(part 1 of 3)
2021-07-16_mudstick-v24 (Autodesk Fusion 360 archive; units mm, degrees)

design "Mudstick" references "N17 48mm", "2298K420_METRIC QUICK-GRIP SCREW-CLAMP BUSHING", "Mudstick Plate"
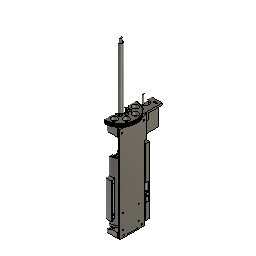
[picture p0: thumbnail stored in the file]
parameter "flexure_w" = 1.5
parameter "gap_w" = 1
parameter "t_sheet_main" = 6.6
parameter "tube_wallthick" = 3.3
parameter "tube_id" = 50.6
parameter "tube_len" = 149.225 (= "( 6 * 25.4 ) * 1 mm - ( 0.125 * 25.4 ) * 1 mm")
parameter "id_bspushbearing" = 40
parameter "od_bspushbearing" = 52
parameter "t_bspushbearing" = 7
parameter "hw_m4insert_d" = 5.8
parameter "hw_m4insert_l" = 4.6
parameter "p_teeth" = 2
parameter "pd_pinion" = 10.1859 (= "p_teeth * nt_pinion / PI")
parameter "pd_driven" = 81.4873 (= "p_teeth * nt_driven / PI")
parameter "belt_length" = 280
parameter "c_dist_manuel" = 56.6
parameter "d101" = 7 (= "t_bspushbearing")
parameter "d118" = 2.15 (= "( 4.3 / 2 ) * 1 mm")
sketch "Sketch1" plane through (0, 0, 0) normal (0, 1, 0) x axis (1, 0, 0)
  line L1 (70, 0) -> (0, 0)
  line L2 (70, -115) -> (70, 0)
  line L3 (0, -115) -> (70, -115)
  line L4 (0, 0) -> (0, -115)
  line L5 (35, 0) -> (35, -115)
  point P1 (0, 0)
  point P2 (0, 0)
  point P6 (35, -115)
  point P7 (35, 0)
  point P4 (70, -115)
  point P5 (0, -115)
  horizontal L1
  vertical L2
  horizontal L3
  coincident P1 P2
  vertical L4
  midpoint L3 P6
  midpoint L1 P7
  dimension "d1" distance P4 P5 = 70
  dimension "d2" distance P2 P5 = 115
extrude "Extrude3" new body sketch "Sketch1" profile of L1 L3 L4 L5 against normal blind 10 bodies "Home Plate"
mirror "Mirror3" mirrorStitchTolerance 0
combine "Combine2"
work_plane "WorkPlane1"
sketch "Revolve" plane through (35, -3.3, 55) normal (-1, 0, 0) x axis (0, 1, 0)
  line L1 (-11.4, 47.1698) -> (-8.1, 47.1698)
  line L2 (-11.4, -102.0552) -> (-11.4, 47.1698)
  line L3 (-36.7, 47.1698) -> (-11.4, 47.1698)
  line L4 (-36.7, -445) -> (-36.7, 155)
  line L5 (-8.1, -102.0552) -> (-8.1, 47.1698)
  line L6 (-11.4, -102.0552) -> (-8.1, -102.0552)
  line L7 (-11.45, 47.2198) -> (-8.1, 47.2198)
  line L8 (-11.45, 41.2198) -> (-11.45, 47.2198)
  line L9 (-13.45, 41.2198) -> (-11.45, 41.2198)
  line L10 (-33.7, 52.9112) -> (-13.45, 41.2198)
  line L11 (-33.7, 67) -> (-33.7, 52.9112)
  line L12 (-8.1, 47.2198) -> (-8.1, 52.2198)
  line L13 (-8.1, 52.2198) -> (-33.7, 67)
  line L14 (-36.7, -42.158) -> (-11.65, -53.839)
  line L15 (-7.7, -158.5398) -> (-10.7, -158.5398)
  line L16 (-10.7, -163.5398) -> (-10.7, -158.5398)
  line L17 (-13.7, -166.5398) -> (-10.7, -163.5398)
  line L18 (-13.7, -170.5398) -> (-13.7, -166.5398)
  line L19 (-10.7, -173.5398) -> (-13.7, -170.5398)
  line L20 (-10.7, -178.5398) -> (-10.7, -173.5398)
  line L21 (-7.7, -178.5398) -> (-10.7, -178.5398)
  line L22 (-7.7, -158.5398) -> (-7.7, -178.5398)
  line L23 (-16.7, -177.2398) -> (-15.4, -178.5398)
  line L24 (-16.7, -162.5398) -> (-16.7, -177.2398)
  line L25 (-25.45, -162.5398) -> (-16.7, -162.5398)
  line L26 (-25.45, -189.0398) -> (-25.45, -162.5398)
  line L27 (-16.7, -159.8398) -> (-16.7, -162.0398)
  line L28 (-15.4, -158.5398) -> (-16.7, -159.8398)
  line L29 (-14.7, -158.5398) -> (-15.4, -158.5398)
  line L30 (-14.7, -155.5398) -> (-14.7, -158.5398)
  line L31 (-25.45, -155.5398) -> (-14.7, -155.5398)
  line L32 (-25.45, -162.0398) -> (-25.45, -155.5398)
  line L33 (-16.7, -162.0398) -> (-25.45, -162.0398)
  line L34 (-14.7, -178.5398) -> (-15.4, -178.5398)
  line L35 (-14.7, -180.0398) -> (-14.7, -178.5398)
  line L36 (4.0437, -189.0398) -> (-25.45, -189.0398)
  line L37 (4.0437, -180.0398) -> (-14.7, -180.0398)
  line L38 (4.0437, -189.0398) -> (4.0437, -180.0398)
  line L39 (-16.7, -165.5398) -> (-12.7, -165.5398)
  line L40 (14.807, -180.0398) -> (14.807, -189.0398)
  line L41 (19.9, -180.0398) -> (14.807, -180.0398)
  line L42 (19.9, -189.0398) -> (19.9, -180.0398)
  line L43 (14.807, -189.0398) -> (19.9, -189.0398)
  line L44 (41.05, -126.5398) -> (-1.25, -126.5398)
  line L45 (41.05, -174.5398) -> (41.05, -126.5398)
  line L46 (-1.25, -174.5398) -> (41.05, -174.5398)
  line L47 (-1.25, -126.5398) -> (-1.25, -174.5398)
  line L48 (41.05, -174.5398) -> (-1.25, -126.5398)
  line L49 (-1.25, -174.5398) -> (41.05, -126.5398)
  line L50 (-32.7, -50.5398) -> (-36.7, -50.5398)
  line L51 (-32.7, -65.5398) -> (-32.7, -50.5398)
  line L52 (-31.7, -65.5398) -> (-32.7, -65.5398)
  line L53 (-30.7, -340.5398) -> (-30.7, -103.5398)
  line L54 (-32.7, -340.5398) -> (-30.7, -340.5398)
  line L55 (-32.7, -350.5398) -> (-32.7, -340.5398)
  line L56 (-36.7, -350.5398) -> (-32.7, -350.5398)
  line L57 (-36.7, -53.1917) -> (-19.0837, -61.4063)
  line L58 (-15.5712, -101.5552) -> (-11.65, -101.5552)
  line L59 (-11.65, -57.5552) -> (-12.4581, -57.5552)
  line L60 (-11.65, -53.839) -> (-11.65, -54.839)
  line L61 (-12.4, -60.3052) -> (-11.65, -59.5552)
  line L62 (-12.4, -95.089) -> (-12.4, -60.3052)
  line L63 (-12.4581, -99.5552) -> (-11.65, -99.5552)
  line L64 (-11.65, -95.839) -> (-11.65, -96.839)
  line L65 (-12.4, -95.089) -> (-11.65, -95.839)
  line L66 (-11.65, -54.839) -> (-12.4581, -54.839)
  line L67 (-11.65, -96.839) -> (-12.4581, -96.839)
  line L68 (-11.65, -96.839) -> (-11.65, -57.5552)
  line L69 (-11.65, -101.5552) -> (-11.65, -96.839)
  line L70 (-16.7, -147.5398) -> (-16.7, -155.5398)
  line L71 (-30.7, -147.5398) -> (-16.7, -147.5398)
  line L72 (-15.5712, -101.5552) -> (-19.0837, -61.4063)
  line L73 (-31.7, -103.5398) -> (-31.7, -65.5398)
  line L74 (-30.7, -103.5398) -> (-31.7, -103.5398)
  line L75 (-25.2, -103.4398) -> (-31.7, -103.4398)
  line L76 (-25.2, -77.4398) -> (-25.2, -103.4398)
  line L77 (-31.7, -77.4398) -> (-25.2, -77.4398)
  line L78 (-31.7, -103.4398) -> (-31.7, -77.4398)
  line L79 (-31.7, -50.4544) -> (-31.7, -55.5233)
  line L80 (-36.7, -48.1229) -> (-31.7, -50.4544)
  line L81 (-25.1, -77.3398) -> (-28.7, -77.3398)
  line L82 (-25.1, -98.4398) -> (-25.1, -77.3398)
  line L83 (-19.3454, -61.2843) -> (-16.0947, -98.4398)
  line L84 (-28.7, -76.3398) -> (-28.7, -77.3398)
  line L85 (-30.7, -73.9563) -> (-28.7, -76.3398)
  line L86 (-30.7, -55.9896) -> (-30.7, -73.9563)
  line L87 (-18.178, -71.7591) -> (-30.7, -65.92)
  line L88 (-15.8391, -98.4929) -> (-12.4581, -98.1971)
  line L89 (-16.0947, -98.4398) -> (-25.1, -98.4398)
  line L90 (4.3937, -188.687) -> (4.3937, -189.0398)
  line L91 (2.8397, -187.7898) -> (4.3937, -188.687)
  line L92 (2.8397, -189.0398) -> (2.8397, -187.7898)
  line L93 (4.3937, -189.0398) -> (4.0437, -189.0398)
  line L94 (-25.45, -184.5398) -> (4.0437, -184.5398)
  line L95 (2.8397, -181.2898) -> (4.3937, -180.3926)
  line L96 (4.3937, -180.0398) -> (4.0437, -180.0398)
  line L97 (4.3937, -180.3926) -> (4.3937, -180.0398)
  line L98 (2.8397, -180.0398) -> (2.8397, -181.2898)
  line L99 (-12.3331, 42.8617) -> (-11.45, 42.8617)
  line L100 (-11.45, 45.5779) -> (-12.3331, 45.5779)
  line L101 (-12.3331, 44.2198) -> (-11.45, 44.2198)
  line L102 (-11.025, 44.2198) -> (-11.45, 44.2198)
  line L103 (-12.3331, 45.5779) -> (-12.3331, 42.8617)
  line L104 (-11.5, -95.989) -> (-11.65, -95.839)
  line L105 (-11.5, -101.5552) -> (-11.5, -95.989)
  line L106 (-11.65, -101.5552) -> (-11.5, -101.5552)
  line L107 (-27.2, 71) -> (-27.2, 63.2472)
  line L108 (-33.7, 71) -> (-27.2, 71)
  line L109 (-33.7, 67) -> (-33.7, 71)
  circle C1 centre (-12.4581, -56.1971) radius 1.3081
  arc A1 centre (-12.4581, -56.1971) radius 1.3581 clockwise from (-12.4581, -57.5552) to (-12.4581, -54.839)
  circle C2 centre (-12.4581, -98.1971) radius 1.3081
  arc A2 centre (-12.4581, -98.1971) radius 1.3581 clockwise from (-12.4581, -99.5552) to (-12.4581, -96.839)
  circle C3 centre (-12.3331, 44.2198) radius 1.3081
  arc A3 centre (-12.3331, 44.2198) radius 1.3581 clockwise from (-12.3331, 42.8617) to (-12.3331, 45.5779)
  point P4 (-11.4, -102.0552)
  point P10 (-11.4, -102.0552)
  point P5 (-36.7, 47.1698)
  point P11 (-8.1, 47.2198)
  point P18 (-8.1, 47.2198)
  point P2 (-8.1, 47.1698)
  point P16 (-33.7, 67)
  point P19 (-33.7, 67)
  point P21 (-36.7, -42.158)
  point P28 (-10.7, -173.5398)
  point P24 (-7.7, -158.5398)
  point P31 (-7.7, -158.5398)
  point P37 (-16.7, -162.0398)
  point P44 (-16.7, -162.0398)
  point P35 (-25.45, -162.5398)
  point P23 (-10.7, -158.5398)
  point P29 (-10.7, -178.5398)
  point P40 (-14.7, -158.5398)
  point P50 (-12.7, -165.5398)
  point P51 (-16.7, -165.5398)
  point P52 (14.807, -189.0398)
  point P56 (14.807, -189.0398)
  point P61 (19.9, -150.5398)
  point P54 (19.9, -180.0398)
  point P49 (4.0437, -189.0398)
  point P48 (4.0437, -180.0398)
  point P62 (-36.7, -50.5398)
  point P68 (-36.7, -350.5398)
  point P71 (-36.7, -53.1917)
  point P73 (-11.15, -56.1971)
  point P72 (-12.4581, -56.1971)
  point P74 (-12.4581, -56.1971)
  point P20 (-11.65, -53.839)
  point P77 (-11.65, -53.839)
  point P78 (-11.65, -59.5552)
  point P81 (-12.4581, -98.1971)
  point P82 (-11.65, -99.5552)
  point P84 (-12.4581, -98.1971)
  point P80 (-12.4, -95.089)
  point P86 (-12.4, -95.089)
  point P76 (-11.65, -57.5552)
  point P90 (-11.65, -96.839)
  point P47 (4.0437, -189.0398)
  point P91 (-16.7, -155.5398)
  point P93 (-30.7, -147.5398)
  point P101 (-31.7, -81.5398)
  point P102 (-31.7, -55.5233)
  point P104 (-36.7, -48.1229)
  point P112 (-30.7, -55.9896)
  point P109 (-19.3454, -61.2843)
  point P113 (-30.7, -65.92)
  point P114 (-18.178, -71.7591)
  point P115 (-12.4581, -98.1971)
  point P116 (-15.8391, -98.4929)
  point P117 (-13.811, -98.3154)
  point P121 (2.8397, -189.0398)
  point P122 (4.0437, -184.5398)
  point P123 (-25.45, -184.5398)
  point P126 (4.0437, -180.0398)
  point P118 (4.3937, -189.0398)
  point P127 (4.3937, -180.0398)
  point P119 (4.3937, -188.687)
  point P124 (4.3937, -180.3926)
  point P120 (2.8397, -187.7898)
  point P125 (2.8397, -181.2898)
  point P128 (2.8397, -180.0398)
  point P130 (-11.45, 42.8617)
  point P129 (-12.3331, 44.2198)
  point P132 (-12.3331, 44.2198)
  point P134 (-11.45, 45.5779)
  point P135 (-11.45, 44.2198)
  point P136 (-12.3331, 44.2198)
  point P137 (-11.025, 44.2198)
  point P140 (-11.65, -101.5552)
  point P22 (-11.65, -101.5552)
  point P141 (-27.2, 63.2472)
  point P144 (-33.7, 67)
  point P8 (3.3, 55)
  point P3 (-11.4, 47.1698)
  point P6 (-36.7, 155)
  point P7 (-36.7, -445)
  point P12 (-11.45, 47.2198)
  point P13 (-11.45, 41.2198)
  point P14 (-13.45, 41.2198)
  point P30 (-7.7, -178.5398)
  point P38 (-16.7, -159.8398)
  point P45 (-14.7, -178.5398)
  point P46 (-14.7, -180.0398)
  point P41 (-14.7, -155.5398)
  point P33 (-16.7, -177.2398)
  point P55 (19.9, -189.0398)
  point P59 (41.05, -174.5398)
  point P60 (-1.25, -174.5398)
  point P58 (41.05, -126.5398)
  point P66 (-32.7, -340.5398)
  point P67 (-32.7, -350.5398)
  point P63 (-32.7, -50.5398)
  point P64 (-32.7, -65.5398)
  point P85 (-11.65, -95.839)
  point P88 (-11.65, -54.839)
  point P42 (-25.45, -155.5398)
  point P92 (-16.7, -147.5398)
  point P17 (-8.1, 52.2198)
  point P15 (-33.7, 52.9112)
  point P69 (-15.5712, -101.5552)
  point P95 (-31.7, -103.5398)
  point P98 (-25.2, -103.4398)
  point P99 (-25.2, -77.4398)
  point P107 (-25.1, -98.4398)
  point P94 (-31.7, -65.5398)
  point P105 (-28.7, -77.3398)
  point P110 (-28.7, -76.3398)
  point P103 (-31.7, -50.4544)
  point P65 (-30.7, -340.5398)
  point P96 (-30.7, -103.5398)
  point P108 (-16.0947, -98.4398)
  point P138 (-11.5, -95.989)
  point P143 (-33.7, 71)
  horizontal L1
  perpendicular L1 L2
  perpendicular L2 L3
  vertical L4
  perpendicular L3 L5
  perpendicular L5 L6
  coincident P4 P10
  coincident P5 L4
  perpendicular L2 L7
  perpendicular L3 L8
  perpendicular L8 L9
  perpendicular L3 L11
  parallel L11 L12
  coincident P11 P18
  coincident P2 L12
  coincident P16 P19
  coincident L4 P21
  perpendicular L58 L68
  horizontal L15
  perpendicular L15 L16
  perpendicular L15 L18
  perpendicular L17 L19
  perpendicular L18 L21
  vertical L20
  equal L16 L20
  coincident L16 P28
  perpendicular L21 L22
  coincident P24 P31
  vertical L24
  perpendicular L24 L25
  perpendicular L25 L26
  perpendicular L25 L27
  perpendicular L27 L29
  perpendicular L29 L30
  perpendicular L30 L31
  perpendicular L31 L32
  perpendicular L32 L33
  coincident P37 P44
  coincident L24 P44
  coincident P35 L32
  horizontal L34
  perpendicular L34 L35
  coincident P23 L29
  perpendicular L26 L36
  coincident P29 L34
  coincident P40 L35
  perpendicular L35 L37
  perpendicular L37 L38
  coincident L17 P50
  coincident L24 P51
  perpendicular L24 L39
  vertical L40
  perpendicular L40 L41
  perpendicular L41 L42
  perpendicular L42 L43
  coincident P52 P56
  perpendicular L44 L45
  parallel L44 L46
  parallel L45 L47
  horizontal L44
  coincident L48 P61
  coincident L49 P61
  vertical P54 P61
  coincident P49 L43
  coincident P48 L41
  coincident L4 P62
  perpendicular L4 L50
  perpendicular L50 L51
  perpendicular L4 L52
  perpendicular L53 L54
  perpendicular L54 L55
  coincident L4 P68
  perpendicular L4 L56
  coincident L4 P71
  coincident C1 P73
  horizontal P72 P73
  vertical L68
  coincident P72 P74
  horizontal L59
  vertical L60
  coincident P20 P77
  tangent A1 L59
  coincident P78 L68
  vertical L62
  vertical P72 P81
  equal C1 C2
  coincident P82 L68
  perpendicular L63 L68
  coincident P81 P84
  tangent L63 A2
  vertical L64
  coincident P80 P86
  coincident P76 L60
  tangent A1 L66
  horizontal L66
  tangent A2 L67
  coincident L64 P90
  horizontal L67
  collinear L68 L69
  coincident P47 P49
  coincident L31 P91
  perpendicular L31 L70
  coincident L53 P93
  perpendicular L53 L71
  perpendicular L52 L73
  perpendicular L53 L74
  horizontal L75
  vertical L76
  horizontal L77
  vertical L78
  coincident L73 P101
  coincident L57 P102
  vertical L79
  coincident L4 P104
  parallel L57 L80
  perpendicular L73 L81
  perpendicular L81 L82
  parallel L72 L83
  perpendicular L81 L84
  coincident L57 P112
  parallel L84 L86
  coincident L57 P109
  coincident L86 P113
  coincident L72 P114
  parallel L57 L87
  coincident P84 P115
  coincident L72 P116
  perpendicular L72 L88
  coincident A2 P117
  coincident L88 P117
  perpendicular L82 L89
  perpendicular L36 L90
  coincident L36 P121
  perpendicular L36 L92
  horizontal L93
  midpoint L38 P122
  coincident L26 P123
  perpendicular L26 L94
  symmetric P49 L94 P126
  symmetric P118 L94 P127
  symmetric P119 L94 P124
  symmetric P120 L94 P125
  symmetric P121 L94 P128
  equal C1 C3
  coincident L8 P130
  coincident P129 P132
  coincident L8 P134
  perpendicular L8 L100
  midpoint L8 P135
  coincident P132 P136
  horizontal L101
  coincident C3 P137
  perpendicular L2 L102
  perpendicular L100 L103
  coincident P132 L103
  horizontal L99
  parallel L65 L104
  parallel L2 L105
  coincident L69 P140
  perpendicular L105 L106
  coincident P22 P140
  coincident L13 P141
  vertical L107
  perpendicular L107 L108
  perpendicular L108 L109
  coincident P19 P144
  dimension "d75" distance L4 P8 = 40
  dimension "d76" distance P2 P3 = 3.3 (= "tube_wallthick")
  dimension "d80" distance L2 L4 = 25.3 (= "tube_id / 2")
  dimension "d81" distance P3 P4 = 149.225 (= "tube_len")
  dimension "d83" distance P6 P8 = 100
  dimension "d84" distance P7 P8 = 500
  dimension "d85" distance L1 L7 = 0.05
  dimension "d86" distance P12 P13 = 6
  dimension "d87" distance L2 L8 = 0.05
  dimension "d88" distance P13 P14 = 2
  dimension "d92" angle L11 L13 = 60
  dimension "d93" distance L4 L11 = 3
  dimension "d96" angle L10 L14 = 5
  dimension "d103" angle L18 L19 = 45
  dimension "d105" distance P28 P29 = 5
  dimension "d106" distance L4 L20 = 26 (= "od_bspushbearing / 2")
  dimension "d112" distance P30 P31 = 20
  dimension "d113" distance L18 P28 = 3
  dimension "d114" distance L25 L33 = 0.5
  dimension "d115" distance L4 L26 = 11.25 (= "( 22 / 2 ) * 1 mm + 0.25 mm")
  dimension "d116" distance L4 L24 = 20 (= "id_bspushbearing / 2")
  dimension "d120" angle L28 L29 = 45
  dimension "d121" distance P38 L29 = 1.3
  dimension "d122" distance L27 L30 = 2
  dimension "d125" distance P45 P46 = 1.5
  dimension "d127" distance P40 P41 = 3
  dimension "d129" angle L23 L24 = 45
  dimension "d130" distance P33 L34 = 1.3 (= "d121")
  dimension "d146" distance L4 L38 = 40.7437 (= "( pd_driven / 2 mm ) * 1 mm")
  dimension "d149" distance P48 P49 = 9
  dimension "d150" distance P23 L39 = 7 (= "t_bspushbearing")
  dimension "d151" distance P55 P56 = 5.093 (= "pd_pinion / 2")
  dimension "d152" distance L4 L42 = 56.6 (= "c_dist_manuel")
  dimension "d153" distance P59 P60 = 42.3
  dimension "d154" distance P58 P59 = 48
  dimension "d155" distance P30 L46 = 4
  dimension "d158" distance P66 P67 = 10
  dimension "d159" distance P67 P68 = 4 (= "( 8 / 2 ) * 1 mm")
  dimension "d160" distance L4 L53 = 6 (= "( 12 / 2 ) * 1 mm")
  dimension "d161" distance P62 P63 = 4 (= "( 8 / 2 ) * 1 mm")
  dimension "d162" distance P63 P64 = 15
  dimension "d165" distance P62 P68 = 300
  dimension "d173" distance L14 L57 = 10
  dimension "d214" diameter C1 = 2.6162
  dimension "d216" distance L2 P73 = 0.25
  dimension "d217" distance C1 A1 = 0.05
  dimension "d220" distance L2 L68 = 0.25
  dimension "d221" angle L61 L68 = 45
  dimension "d222" distance P76 P78 = 2
  dimension "d223" distance L2 L62 = 1
  dimension "d225" distance L58 P82 = 2
  dimension "d226" distance C2 A2 = 0.05
  dimension "d228" angle L64 L65 = 45
  dimension "d229" distance P85 P90 = 1
  dimension "d230" distance P77 P88 = 1
  dimension "d234" distance L4 P49 = 40.7437
  dimension "d235" distance P42 L36 = 33.5
  dimension "d240" distance P23 L25 = 4
  dimension "d246" distance L4 P41 = 22
  dimension "d247" distance L4 L70 = 20 (= "( 40 / 2 ) * 1 mm")
  dimension "d248" distance P91 P92 = 8
  dimension "d266" distance P8 P19 = 12
  dimension "d280" distance P4 L58 = 0.5
  dimension "d281" distance P17 P18 = 5
  dimension "d285" distance P15 L14 = 87.4298
  dimension "d286" angle L10 L11 = 60
  dimension "d288" distance P62 P69 = 51.0154
  dimension "d289" distance L4 L73 = 5 (= "( 10 / 2 ) * 1 mm")
  dimension "d290" distance L50 P95 = 53
  dimension "d291" distance L4 L76 = 11.5 (= "( 23 / 2 ) * 1 mm")
  dimension "d292" distance P98 P99 = 26
  dimension "d293" distance L4 L78 = 5 (= "( 10 / 2 ) * 1 mm")
  dimension "d294" distance L52 P101 = 16
  dimension "d298" distance P63 L79 = 1
  dimension "d301" distance P95 L75 = 0.1
  dimension "d302" angle L58 L72 = 95
  dimension "d303" distance P69 L83 = 0.25
  dimension "d305" distance L76 P107 = 0.1
  dimension "d306" distance P99 L81 = 0.1
  dimension "d307" distance P99 L84 = 3.5
  dimension "d308" distance P94 L86 = 1
  dimension "d309" angle L84 L85 = 40
  dimension "d310" distance P105 P110 = 1
  dimension "d311" distance P112 L87 = 9
  dimension "d312" distance P116 P117 = 2.0358
  dimension "d315" distance P19 L21 = 245.5398
  dimension "d317" distance P72 P84 = 42
  dimension "d318" distance P63 L80 = 0.5
  dimension "d319" distance L14 P103 = 5.406
  dimension "d320" distance L36 P65 = 151.5
  dimension "d321" distance L71 P96 = 44
  dimension "d322" distance P98 L89 = 5
  dimension "d356" distance P47 L92 = 1.204 (= "0.75 mm + 0.254 mm + 0.2 mm")
  dimension "d357" distance P49 P118 = 0.35
  dimension "d358" distance P120 P121 = 1.25
  dimension "d359" angle L91 L92 = 60
  dimension "d453" distance L4 L22 = 29
  dimension "d551" distance C3 A3 = 0.05
  dimension "d563" distance L4 P108 = 20.6053
  dimension "d564" distance L2 P137 = 0.375
  dimension "d566" distance L2 P138 = 0.1
  dimension "d567" distance P143 P144 = 4
  dimension "d568" distance L4 L107 = 9.5
revolve "Revolve1" sketch "Revolve" AlongAngle 360 bodies "Nozzle", "Canister", "Drive Housing", "Drive", "Drive Cap", "Ball Screw"
fillet "Fillet22" radius 30
fillet "Fillet35" radius 5
chamfer "Chamfer13" distance 4
revolve "Revolve2" sketch "Revolve" AlongAngle 30 (= "( 360 / 12 ) * 1 deg") AgainstAngle 30 (= "( 360 / 12 ) * 1 deg")
chamfer "Chamfer3" distance 8 distance 5
revolve "Revolve3" sketch "Revolve" AlongAngle 360
circular_pattern "C-Pattern1" TotalAngle 360
combine "Combine3"
combine "Combine4"
combine "Combine6"
component_insert "Component Insert1"
joint "Assemble1" alignAngle 0 alignOffsetX 0 alignOffsetY 0 alignOffsetZ 0
sketch "Drive Tooth" plane through (0, 0, 244.0398) normal (0, 0, 1) x axis (-1, 0, 0)
  line L1 (-75.7437, 40) -> (-35, 40)
  line L2 (-75.7314, 39.0001) -> (-35, 40)
  line L3 (-71.7147, 55.2077) -> (-35, 40)
  circle C1 centre (-35, 40) radius 40.7437
  circle C2 centre (-35, 40) radius 11.25
  circle C3 centre (-35, 40) radius 40.7437
  circle C4 centre (-35, 40) radius 40.4897
  circle C5 centre (-35, 40) radius 39.7397
  arc A1 centre (-75.2897, 40) radius 0.55 clockwise from (-74.7397, 40) to (-75.0377, 39.5111)
  arc A2 centre (-75.4958, 40.4) radius 1 clockwise from (-75.0377, 39.5111) to (-75.3542, 39.4101)
  arc A3 centre (-75.3329, 39.2616) radius 0.15 clockwise from (-75.4829, 39.2589) to (-75.3542, 39.4101)
  circle C6 centre (-62.1342, 51.2393) radius 7.3698
  point P3 (-35, 40)
  point P4 (-35, 40)
  point P5 (-75.7437, 40)
  point P6 (-35, 40)
  point P7 (-75.7314, 39.0001)
  point P10 (-74.7397, 40)
  point P15 (-75.4829, 39.2589)
  point P14 (-75.3542, 39.4101)
  point P16 (-75.3542, 39.4101)
  point P9 (-35, 40)
  point P20 (-35, 40)
  point P21 (-71.7147, 55.2077)
  point P18 (-62.1342, 51.2393)
  point P22 (-68.943, 54.0597)
  point P23 (-55.3253, 48.419)
  point P13 (-75.4958, 40.4)
  point P8 (-35, 40)
  concentric C1 C3
  coincident P3 P4
  coincident C1 P5
  horizontal L1
  coincident P3 P6
  coincident C1 P7
  concentric C3 C4
  concentric C3 C5
  tangent C5 A1
  coincident L1 P10
  coincident C5 P10
  tangent A1 A2
  tangent A2 A3
  coincident C4 P15
  coincident P14 P16
  tangent C4 A3
  coincident P9 P20
  coincident C5 P21
  coincident P18 L3
  coincident C6 P22
  coincident L3 P22
  coincident C6 P23
  coincident L3 P23
  dimension "d337" diameter C3 = 81.4873 (= "pd_driven")
  dimension "d338" angle L1 L2 = 1.406 (= "( 180 / nt_driven ) * 1 deg")
  dimension "d342" distance C4 C5 = 0.75
  dimension "d345" distance C3 C4 = 0.254
  dimension "d346" radius A1 = 0.55
  dimension "d347" radius A2 = 1
  dimension "d348" distance L1 P13 = 0.4
  dimension "d349" radius A3 = 0.15
  dimension "d413" angle L1 L3 = 22.5 (= "( 180 / 8 ) * 1 deg")
  dimension "d414" distance P21 P22 = 3
  dimension "d415" distance P8 P23 = 22
extrude "Extrude6" new body sketch "Drive Tooth" profile of C1 L1 L2 C4 A1 A2 A3 to an object
mirror "Mirror4" mirrorStitchTolerance 0.1
circular_pattern "C-Pattern4" TotalAngle 360
combine "Combine7"
revolve "Revolve6" sketch "Revolve" AlongAngle 360
extrude "Extrude7" cut sketch "Drive Tooth" profile of L1 L2 C6 to an object
circular_pattern "C-Pattern5" TotalAngle 360
sketch "Lead Nut Mount" plane through (0, 0, 210.5398) normal (0, 0, -1) x axis (1, 0, 0)
  line L1 (35, 24) -> (35, 40)
  line L2 (30.9585, 24) -> (32.9793, 27.5)
  line L3 (32.9793, 20.5) -> (30.9585, 24)
  line L4 (37.0207, 20.5) -> (32.9793, 20.5)
  line L5 (39.0415, 24) -> (37.0207, 20.5)
  line L6 (37.0207, 27.5) -> (39.0415, 24)
  line L7 (32.9793, 27.5) -> (37.0207, 27.5)
  circle C1 centre (35, 40) radius 11.25
  circle C2 centre (35, 40) radius 22
  circle C3 centre (35, 24) radius 2.125
  point P2 (35, 40)
  point P3 (35, 40)
  point P4 (35, 24)
  point P5 (35, 24)
  point P12 (35, 24)
  point P8 (32.9793, 20.5)
  coincident P2 P3
  vertical L1
  coincident P4 P5
  coincident P4 P12
  horizontal L7
  dimension "d402" distance P3 P4 = 16
  dimension "d403" diameter C3 = 4.25
  dimension "d404" distance P8 L7 = 7
extrude "Extrude11" cut sketch "Lead Nut Mount" profile of C3 to an object
extrude "Extrude12" cut sketch "Lead Nut Mount" profile of C3 L2 L3 L4 L5 L6 L7 to an object from offset -26 (= "-34 mm + 8 mm")
chamfer "Chamfer7" distance 0.5
circular_pattern "C-Pattern6" TotalAngle 360
chamfer "Chamfer12" distance 1.7
sketch "Motor Setup" plane through (0, 0, 233.5398) normal (0, 0, 1) x axis (-1, 0, 0)
  line L1 (-14.167, 5.7407) -> (-57.3407, 4.233)
  line L2 (-12.6593, -37.433) -> (-14.167, 5.7407)
  line L3 (-55.833, -38.9407) -> (-12.6593, -37.433)
  line L4 (-57.3407, 4.233) -> (-55.833, -38.9407)
  line L5 (-12.6593, -37.433) -> (-57.3407, 4.233)
  line L6 (-20.0504, -0.5685) -> (-51.0315, -1.6504)
  line L7 (-18.9685, -31.5496) -> (-20.0504, -0.5685)
  line L8 (-49.9496, -32.6315) -> (-18.9685, -31.5496)
  line L9 (-51.0315, -1.6504) -> (-49.9496, -32.6315)
  line L10 (-20.0504, -0.5685) -> (-49.9496, -32.6315)
  line L11 (-35, 4.55) -> (-35, -37.75)
  line L12 (-51.0315, -1.6504) -> (-37.7646, -19.1)
  line L13 (-55.2142, -32.3669) -> (-51.0315, -1.6504)
  line L14 (-20.315, -5.8331) -> (-51.0315, -1.6504)
  line L15 (-62, -40.4407) -> (-62, 73)
  line L16 (-8, -40.4407) -> (-62, -40.4407)
  line L17 (-8, 73) -> (-8, -40.4407)
  line L18 (-13.7022, 6.7575) -> (-12.054, -40.4407)
  line L19 (-58.375, 5.1975) -> (-13.7022, 6.7575)
  line L20 (-60, -6.3652) -> (-58.375, 5.1975)
  line L21 (-62, -6.3652) -> (-60, -6.3652)
  line L22 (-8, 73) -> (-62, 73)
  line L23 (-35, 73) -> (-35, 40)
  circle C1 centre (-35, 40) radius 29
  circle C2 centre (-35, 40) radius 26
  circle C3 centre (-51.0315, -1.6504) radius 1.625
  arc A1 centre (-51.0315, -1.6504) radius 32.9703 clockwise from (-26.9185, -24.1361) to (-31.0768, -27.8963)
  arc A2 centre (-37.7646, -19.1) radius 11.05 clockwise from (-31.0768, -27.8963) to (-44.4524, -10.3037)
  arc A3 centre (-51.0315, -1.6504) radius 10.8703 clockwise from (-43.0815, -9.0639) to (-44.4524, -10.3037)
  arc A4 centre (-35, -16.6) radius 11.05 clockwise from (-43.0815, -9.0639) to (-26.9185, -24.1361)
  arc A5 centre (-51.0315, -1.6504) radius 21.9203 clockwise from (-35, -16.6) to (-37.7646, -19.1)
  arc A6 centre (-51.0315, -1.6504) radius 32.625 clockwise from (-18.4264, -0.5118) to (-18.7048, -6.0523)
  arc A7 centre (-20.315, -5.8331) radius 1.625 clockwise from (-18.7048, -6.0523) to (-21.9251, -5.6138)
  arc A8 centre (-51.0315, -1.6504) radius 29.375 clockwise from (-21.6744, -0.6252) to (-21.9251, -5.6138)
  arc A9 centre (-20.0504, -0.5685) radius 1.625 clockwise from (-21.6744, -0.6252) to (-18.4264, -0.5118)
  arc A10 centre (-51.0315, -1.6504) radius 31 clockwise from (-20.0504, -0.5685) to (-20.315, -5.8331)
  arc A11 centre (-51.0315, -1.6504) radius 45.4656 clockwise from (-17.7801, -32.6579) to (-23.5142, -37.8432)
  arc A12 centre (-24.4977, -36.5496) radius 1.625 clockwise from (-23.5142, -37.8432) to (-25.4812, -35.256)
  arc A13 centre (-51.0315, -1.6504) radius 42.2156 clockwise from (-20.1569, -30.4414) to (-25.4812, -35.256)
  arc A14 centre (-18.9685, -31.5496) radius 1.625 clockwise from (-20.1569, -30.4414) to (-17.7801, -32.6579)
  arc A15 centre (-51.0315, -1.6504) radius 43.8406 clockwise from (-18.9685, -31.5496) to (-24.4977, -36.5496)
  arc A16 centre (-51.0315, -1.6504) radius 32.625 clockwise from (-49.8929, -34.2555) to (-55.4335, -33.9771)
  arc A17 centre (-55.2142, -32.3669) radius 1.625 clockwise from (-55.4335, -33.9771) to (-54.995, -30.7568)
  arc A18 centre (-51.0315, -1.6504) radius 29.375 clockwise from (-50.0063, -31.0075) to (-54.995, -30.7568)
  arc A19 centre (-49.9496, -32.6315) radius 1.625 clockwise from (-50.0063, -31.0075) to (-49.8929, -34.2555)
  arc A20 centre (-51.0315, -1.6504) radius 31 clockwise from (-49.9496, -32.6315) to (-55.2142, -32.3669)
  point P7 (-35, -16.6)
  point P8 (-51.0315, -1.6504)
  point P14 (-51.0315, -1.6504)
  point P21 (-51.0315, -1.6504)
  point P19 (-35, -16.6)
  point P20 (-37.7646, -19.1)
  point P22 (-37.7646, -19.1)
  point P23 (-51.0315, -1.6504)
  point P30 (-51.0315, -1.6504)
  point P9 (-20.0504, -0.5685)
  point P28 (-20.0504, -0.5685)
  point P37 (-51.0315, -1.6504)
  point P10 (-18.9685, -31.5496)
  point P35 (-18.9685, -31.5496)
  point P44 (-51.0315, -1.6504)
  point P11 (-49.9496, -32.6315)
  point P42 (-49.9496, -32.6315)
  point P36 (-24.4977, -36.5496)
  point P45 (-51.0315, -1.6504)
  point P43 (-55.2142, -32.3669)
  point P46 (-55.2142, -32.3669)
  point P29 (-20.315, -5.8331)
  point P47 (-20.315, -5.8331)
  point P53 (-12.054, -40.4407)
  point P57 (-62, -6.3652)
  point P2 (-35, 40)
  point P58 (-35, 40)
  point P59 (-35, 73)
  point P60 (-35, 69)
  point P3 (-57.3407, 4.233)
  point P6 (-55.833, -38.9407)
  point P51 (-8, 73)
  point P4 (-14.167, 5.7407)
  point P55 (-58.375, 5.1975)
  point P56 (-60, -6.3652)
  perpendicular L1 L2
  parallel L1 L3
  parallel L2 L4
  equal L1 L4
  midpoint P7 L5
  perpendicular L6 L7
  parallel L6 L8
  parallel L7 L9
  parallel L1 L6
  coincident L5 P8
  midpoint P7 L10
  coincident P8 P14
  tangent A1 A2
  tangent A2 A3
  tangent A3 A4
  tangent A1 A4
  coincident P14 P21
  coincident P7 P19
  coincident P20 P22
  coincident P21 P23
  tangent A6 A7
  tangent A7 A8
  tangent A8 A9
  tangent A6 A9
  coincident P21 P30
  coincident P9 P28
  tangent A11 A12
  tangent A12 A13
  tangent A13 A14
  tangent A11 A14
  coincident P14 P37
  coincident P10 P35
  tangent A16 A17
  tangent A17 A18
  tangent A18 A19
  tangent A16 A19
  coincident P14 P44
  coincident P11 P42
  equal C3 A19
  equal C3 A9
  equal C3 A14
  coincident L12 P36
  coincident P37 P45
  coincident P43 P46
  coincident P29 P47
  vertical L15
  perpendicular L15 L16
  perpendicular L16 L17
  perpendicular L18 L19
  parallel L2 L18
  coincident L16 P53
  coincident L15 P57
  perpendicular L15 L21
  perpendicular L17 L22
  coincident P2 P58
  midpoint L22 P59
  vertical L23
  coincident C1 P60
  coincident L23 P60
  dimension "d361" distance P3 P6 = 43.2
  dimension "d362" distance P8 P11 = 31
  dimension "d370" angle L6 L11 = 92
  dimension "d371" diameter C3 = 3.25
  dimension "d372" radius A4 = 11.05 (= "( 22.1 / 2 ) * 1 mm")
  dimension "d373" distance P19 P20 = 2.5
  dimension "d374" = 9.8
  dimension "d375" angle L12 L13 = 45
  dimension "d376" angle L12 L14 = 45
  dimension "d378" distance L15 P51 = 54
  dimension "d379" distance P6 L16 = 1.5
  dimension "d382" distance P4 L18 = 0.5
  dimension "d384" distance P4 L19 = 1
  dimension "d385" angle L19 L20 = 100 (= "90 deg + 10 deg")
  dimension "d386" distance L4 P55 = 1
  dimension "d387" distance P56 P57 = 2
  dimension "d393" distance P59 P60 = 4
extrude "Extrude17" cut sketch "Motor Setup" profile of C1 L15 L17 to an object
extrude "Extrude9" add sketch "Motor Setup" profile of C1 L15 L16 L17 L18 L19 L20 L21 L22 to an object
extrude "Extrude10" add sketch "Motor Setup" profile of C3 A1 A2 A3 A4 A6 A7 A8 A9 A11 A12 A13 A14 A16 A17 A18 A19 L16 L18 L19 L20 against normal blind 5
fillet "Fillet27" radius 0.5
fillet "Fillet28" radius 3
fillet "Fillet29" radius 1
component_insert "Component Insert2"
joint "Assemble2" alignAngle 90 alignOffsetX 0 alignOffsetY 0 alignOffsetZ 0
sketch "Nozzle Cup Revolve" plane through (35, -5, 57.5) normal (-1, 0, 0) x axis (0, 1, 0)
  line L1 (-6.4, 54.7198) -> (-32, 69.5)
  line L2 (-22.5, 68.5) -> (-22.5, 64.0152)
  line L3 (-5.9, 68.5) -> (-22.5, 68.5)
  line L4 (-5.9, 55.7198) -> (-5.9, 68.5)
  line L5 (-8.1321, 55.7198) -> (-5.9, 55.7198)
  line L6 (-35, -442.5) -> (-35, 157.5)
  point P4 (-22.5, 64.0152)
  point P8 (-8.1321, 55.7198)
  point P3 (-6.4, 54.7198)
  point P2 (-32, 69.5)
  coincident L1 P4
  vertical L2
  perpendicular L2 L3
  perpendicular L3 L4
  coincident L1 P8
  perpendicular L4 L5
  dimension "d420" distance P3 L4 = 0.5
  dimension "d421" distance P3 L5 = 1
  dimension "d422" distance P2 L3 = 1
  dimension "d565" distance L2 L6 = 12.5
revolve "Revolve7" sketch "Nozzle Cup Revolve" AlongAngle 360 bodies "Lower Cup"
sketch "Nozzle Cup Square Out" plane through (0, 0, -11) normal (0, 0, -1) x axis (1, 0, 0)
  line L1 (8, 73) -> (8, -40.4407)
  line L2 (62, 73) -> (8, 73)
  line L3 (62, 10.5) -> (62, 73)
  line L4 (8, 10.5) -> (62, 10.5)
  line L5 (35, 73) -> (35, 40)
  line L6 (70, 10) -> (0, 10)
  circle C1 centre (35, 40) radius 12.5
  circle C2 centre (35, 40) radius 29.1
  point P4 (8, 73)
  point P5 (8, 73)
  point P8 (8, 10.5)
  point P9 (35, 40)
  point P10 (35, 40)
  point P11 (35, 73)
  coincident P4 P5
  perpendicular L1 L2
  perpendicular L2 L3
  coincident L1 P8
  perpendicular L1 L4
  coincident P9 P10
  midpoint L2 P11
  vertical L5
  dimension "d440" distance L4 L6 = 0.5
extrude "Extrude18" cut sketch "Nozzle Cup Square Out" profile of C2 L1 L3 to an object
extrude "Extrude14" add sketch "Nozzle Cup Square Out" profile of C2 L1 L2 L3 L4 to an object
sketch "Wing" plane through (8, 0, 0) normal (-1, 0, 0) x axis (0, -1, 0)
  line L1 (73, 213.5398) -> (-40.4407, 213.5398)
  line L2 (-40.4407, 233.5398) -> (73, 233.5398)
  line L3 (73, -11) -> (73, 213.5398)
  line L4 (73, -11) -> (10.5, -11)
  line L5 (10.5, 213.5398) -> (10.5, 1.7802)
  line L6 (20.5415, -5) -> (18.5207, -8.5)
  line L7 (18.5207, -1.5) -> (20.5415, -5)
  line L8 (14.4793, -1.5) -> (18.5207, -1.5)
  line L9 (12.4585, -5) -> (14.4793, -1.5)
  line L10 (14.4793, -8.5) -> (12.4585, -5)
  line L11 (18.5207, -8.5) -> (14.4793, -8.5)
  line L12 (9.9793, 227.0398) -> (14.0207, 227.0398)
  line L13 (16.0415, 223.5398) -> (14.0207, 220.0398)
  line L14 (14.0207, 220.0398) -> (9.9793, 220.0398)
  line L15 (9.9793, 220.0398) -> (7.9585, 223.5398)
  line L16 (7.9585, 223.5398) -> (9.9793, 227.0398)
  line L17 (14.0207, 227.0398) -> (16.0415, 223.5398)
  line L18 (17, 225.5398) -> (17, 221.5398)
  line L19 (40, 500) -> (40, -100)
  line L20 (63, 225.5398) -> (63, 221.5398)
  line L21 (17, 223.5398) -> (12, 223.5398)
  line L22 (65.9793, 220.0398) -> (70.0207, 220.0398)
  line L23 (65.9793, 227.0398) -> (63.9585, 223.5398)
  line L24 (72.0415, 223.5398) -> (70.0207, 227.0398)
  line L25 (70.0207, 220.0398) -> (72.0415, 223.5398)
  line L26 (70.0207, 227.0398) -> (65.9793, 227.0398)
  line L27 (63.9585, 223.5398) -> (65.9793, 220.0398)
  line L28 (27.5, 230.5398) -> (27.5, 233.5398)
  line L29 (52.5, 230.5398) -> (27.5, 230.5398)
  line L30 (52.5, 233.5398) -> (52.5, 230.5398)
  line L31 (4, 178.5398) -> (4, 233.5398)
  line L32 (10.5, 178.5398) -> (4, 178.5398)
  line L33 (-40.4407, 213.5398) -> (-40.4407, 233.5398)
  line L34 (61.4793, -8.5) -> (65.5207, -8.5)
  line L35 (65.5207, -1.5) -> (61.4793, -1.5)
  line L36 (59.4585, -5) -> (61.4793, -8.5)
  line L37 (61.4793, -1.5) -> (59.4585, -5)
  line L38 (67.5415, -5) -> (65.5207, -1.5)
  line L39 (65.5207, -8.5) -> (67.5415, -5)
  line L40 (27.5, -8) -> (27.5, -11)
  line L41 (52.5, -8) -> (27.5, -8)
  line L42 (52.5, -11) -> (52.5, -8)
  line L43 (73, 233.5398) -> (73, 213.5398)
  line L44 (20, 16) -> (10.1, 16)
  line L45 (20, 4) -> (20, 16)
  line L46 (10.1, 4) -> (20, 4)
  line L47 (10.1, 16) -> (10.1, 4)
  line L48 (10.5, 1.7802) -> (10.5, -11)
  circle C1 centre (16.5, -5) radius 2.125
  circle C2 centre (12, 223.5398) radius 2.125
  circle C3 centre (68, 223.5398) radius 2.125
  circle C4 centre (63.5, -5) radius 2.125
  point P4 (73, 213.5398)
  point P6 (73, 213.5398)
  point P7 (73, -11)
  point P9 (73, -11)
  point P11 (10.5, 213.5398)
  point P12 (16.5, -5)
  point P19 (16.5, -5)
  point P20 (12, 223.5398)
  point P23 (12, 223.5398)
  point P28 (17, 221.5398)
  point P32 (63, 221.5398)
  point P29 (17, 225.5398)
  point P33 (63, 225.5398)
  point P34 (12, 223.5398)
  point P35 (17, 223.5398)
  point P21 (9.9793, 227.0398)
  point P41 (70.0207, 227.0398)
  point P22 (9.9793, 220.0398)
  point P37 (70.0207, 220.0398)
  point P36 (68, 223.5398)
  point P24 (14.0207, 227.0398)
  point P39 (65.9793, 227.0398)
  point P25 (16.0415, 223.5398)
  point P44 (63.9585, 223.5398)
  point P26 (7.9585, 223.5398)
  point P42 (72.0415, 223.5398)
  point P27 (14.0207, 220.0398)
  point P38 (65.9793, 220.0398)
  point P40 (68, 223.5398)
  point P45 (27.5, 233.5398)
  point P48 (52.5, 233.5398)
  point P49 (40, 230.5398)
  point P50 (4, 233.5398)
  point P52 (10.5, 178.5398)
  point P13 (18.5207, -8.5)
  point P60 (61.4793, -8.5)
  point P14 (20.5415, -5)
  point P54 (59.4585, -5)
  point P15 (18.5207, -1.5)
  point P56 (61.4793, -1.5)
  point P16 (14.4793, -1.5)
  point P59 (65.5207, -1.5)
  point P17 (12.4585, -5)
  point P58 (67.5415, -5)
  point P18 (14.4793, -8.5)
  point P55 (65.5207, -8.5)
  point P53 (63.5, -5)
  point P61 (27.5, -11)
  point P64 (52.5, -11)
  point P65 (40, -8)
  point P71 (20, 10)
  point P10 (10.5, 1.7802)
  point P73 (10.5, 1.7802)
  point P8 (10.5, -11)
  point P72 (10.5, -11)
  point P46 (27.5, 230.5398)
  point P47 (52.5, 230.5398)
  point P51 (4, 178.5398)
  point P70 (10, 0)
  point P67 (20, 16)
  point P68 (20, 4)
  point P1 (0, 0)
  coincident P4 P6
  perpendicular L1 L3
  coincident P7 P9
  perpendicular L4 L5
  coincident L1 P11
  coincident P12 P19
  horizontal L11
  coincident P20 P23
  horizontal L14
  symmetric P28 L19 P32
  symmetric P29 L19 P33
  coincident P23 P34
  midpoint L18 P35
  horizontal L21
  symmetric P21 L19 P41
  symmetric P22 L19 P37
  symmetric P23 L19 P36
  symmetric P24 L19 P39
  symmetric P25 L19 P44
  symmetric P26 L19 P42
  symmetric P27 L19 P38
  symmetric C2 L19 C3
  symmetric L19 P34 P40
  coincident L2 P45
  perpendicular L2 L28
  perpendicular L28 L29
  coincident L2 P48
  perpendicular L2 L30
  midpoint L29 P49
  coincident L19 P49
  coincident L2 P50
  perpendicular L1 L31
  coincident L5 P52
  perpendicular L5 L32
  symmetric C1 L19 C4
  symmetric P13 L19 P60
  symmetric P14 L19 P54
  symmetric P15 L19 P56
  symmetric P16 L19 P59
  symmetric P17 L19 P58
  symmetric P18 L19 P55
  symmetric P19 L19 P53
  coincident L4 P61
  perpendicular L4 L40
  perpendicular L40 L41
  coincident L4 P64
  perpendicular L4 L42
  coincident L41 P65
  midpoint L41 P65
  coincident L19 P65
  equal L29 L41
  equal L30 L42
  horizontal L44
  vertical L45
  horizontal L46
  vertical L47
  midpoint L45 P71
  coincident P10 P73
  coincident P8 P72
  horizontal L4
  dimension "d427" diameter C1 = 4.25
  dimension "d428" distance P16 L11 = 7
  dimension "d429" distance L4 P19 = 6
  dimension "d431" diameter C2 = 4.25
  dimension "d432" distance P21 L14 = 7
  dimension "d433" distance P34 P35 = 5
  dimension "d434" distance P45 P46 = 3
  dimension "d435" distance P46 P47 = 25
  dimension "d436" distance P50 P51 = 55
  dimension "d437" distance P23 L31 = 8
  dimension "d462" distance L47 P70 = 0.1
  dimension "d463" distance P67 P68 = 12
  dimension "d464" distance P1 P67 = 20
  dimension "d465" distance P1 P71 = 10
  dimension "d486" distance P19 L48 = 6
extrude "Extrude13" cut sketch "Wing" profile of C1 C2 C3 C4 to an object
sketch "Pull Out Relief" plane through (0, -73, 0) normal (0, -1, 0) x axis (1, 0, 0)
  line L1 (8, 1.7802) -> (62, 1.7802)
  line L2 (8, -11) -> (8, 1.7802)
  line L3 (62, -11) -> (8, -11)
  line L4 (62, 1.7802) -> (62, -11)
  line L5 (29, -2) -> (22.4526, 1.7802)
  line L6 (41, -2) -> (29, -2)
  line L7 (47.5474, 1.7802) -> (41, -2)
  line L8 (35, -2) -> (35, 1.7802)
  point P6 (22.4526, 1.7802)
  point P9 (47.5474, 1.7802)
  point P10 (35, 1.7802)
  point P11 (35, -2)
  point P7 (29, -2)
  point P8 (41, -2)
  point P12 (8, -5)
  coincident L1 P6
  parallel L1 L6
  coincident L1 P9
  midpoint L1 P10
  midpoint L6 P11
  vertical L8
  dimension "d445" distance P7 P8 = 12
  dimension "d446" angle L5 L6 = 30
  dimension "d447" angle L6 L7 = 30 (= "d446")
  dimension "d450" distance L6 P12 = 3
extrude "Extrude15" cut sketch "Pull Out Relief" profile of L1 L5 L6 L7 to an object
fillet "Fillet31" radius 12
extrude "Extrude16" new body sketch "Wing" profile of L1 L2 L3 L4 L5 C1 L6 L7 L8 L9 L10 L11 L12 L13 L14 L15 L16 L17 C2 L22 L23 C3 L24 L25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 blind 5 from offset 0.1 bodies "West Wing"
offset_faces "OffsetFaces3" distance -0.15
extrude "Extrude21" add sketch "Wing" profile of L2 L4 L28 L29 L30 L40 L41 L42 to an object
mirror "Mirror6" mirrorStitchTolerance 0.1 bodies "Drive Housing (1)"
combine "Combine9"
combine "Combine10" bodies "Drive Housing (1)"
extrude "Extrude22" of existing geometry to an object
offset_faces "OffsetFaces4" distance -0.5
sketch "Sketch14" plane through (0, 0, 213.5398) normal (0, 0, -1) x axis (1, 0, 0)
  line L1 (7.9, 50.6019) -> (7.9, 29.3981)
  line L2 (5.9, 73) -> (5.9, 40)
  line L3 (7.9, 73) -> (5.9, 73)
  line L4 (7.9, 73) -> (7.9, 50.6019)
  arc A1 centre (35, 40) radius 29.1 clockwise from (7.9, 29.3981) to (7.9, 50.6019)
  point P5 (5.9, 40)
  point P3 (7.9, 50.6019)
  point P8 (7.9, 50.6019)
  point P7 (7.9, 73)
  point P9 (7.9, 73)
  point P10 (8, 73)
  midpoint A1 P5
  tangent A1 L2
  vertical L2
  coincident P3 P8
  parallel L1 L4
  coincident P7 P9
  horizontal L3
  coincident L3 P10
extrude "Extrude23" cut sketch "Sketch14" to an object
sketch "Sketch15" plane through (0, 0, 1.7802) normal (0, 0, 1) x axis (-1, 0, 0)
  curve K1 (-22.4526, 67.1347) -> (-19.8384, 62.1813)
  curve K2 (-50.1616, 62.1813) -> (-47.5474, 67.1347)
  line L1 (-47.5474, 73) -> (-47.5474, 67.1347)
  line L2 (-62, 73) -> (-47.5474, 73)
  line L3 (-62, 10.5) -> (-62, 73)
  line L4 (-8, 10.5) -> (-62, 10.5)
  line L5 (-8, 73) -> (-8, 10.5)
  line L6 (-22.4526, 73) -> (-8, 73)
  line L7 (-22.4526, 67.1347) -> (-22.4526, 73)
  line L8 (-35, 10.5) -> (-35, 40)
  line L9 (-13, 16) -> (-13, 10.5)
  line L10 (-17, 16) -> (-9, 16)
  line L11 (-26.7296, 10.1) -> (-26.7296, 12.1)
  line L12 (-35, 10.1) -> (-35, 10.5)
  line L13 (-2.9, 10.1) -> (-35, 10.1)
  line L14 (-2.9, 10.5) -> (-2.9, 10.1)
  line L15 (-8, 10.5) -> (-2.9, 10.5)
  line L16 (-7.9, 10.5) -> (-7.9, 29.3981)
  arc A1 centre (-35, 40) radius 26.8679 clockwise from (-19.8384, 62.1813) to (-50.1616, 62.1813)
  arc A2 centre (-35, 40) radius 29.1 clockwise from (-5.9, 40) to (-7.9, 29.3981)
  arc A3 centre (-35, 40) radius 29.1 clockwise from (-7.9, 29.3981) to (-35, 10.9)
  point P13 (-7.9, 29.3981)
  point P18 (-7.9, 29.3981)
  point P15 (-35, 40)
  point P16 (-35, 40)
  point P19 (-35, 40)
  point P20 (-35, 10.5)
  point P17 (-35, 10.9)
  point P21 (-13, 10.5)
  point P22 (-13, 16)
  point P25 (-26.7296, 12.1)
  point P10 (-8, 10.5)
  point P30 (-8, 10.5)
  point P29 (-2.9, 10.5)
  point P31 (-2.9, 10.5)
  point P26 (-26.7296, 10.1)
  point P33 (-7.9, 29.3981)
  point P34 (-7.9, 10.5)
  point P23 (-9, 16)
  point P24 (-17, 16)
  point P32 (0, 10)
  coincident P13 P18
  coincident P15 P16
  coincident P15 P19
  midpoint L4 P20
  coincident P17 L8
  coincident L4 P21
  perpendicular L4 L9
  horizontal L10
  midpoint P22 L10
  coincident A3 P25
  perpendicular L4 L11
  perpendicular L4 L12
  perpendicular L12 L13
  perpendicular L13 L14
  perpendicular L12 L15
  coincident P10 P30
  coincident P29 P31
  coincident P26 L13
  coincident P13 P33
  coincident L15 P34
  perpendicular L15 L16
  dimension "d487" distance P23 P24 = 8
  dimension "d488" distance L8 L9 = 22
  dimension "d489" distance P21 P22 = 5.5
  dimension "d490" distance P25 P26 = 2
  dimension "d494" distance L13 P32 = 0.1
extrude "Extrude24" new body sketch "Sketch15" profile of L4 L5 A3 L11 L13 L14 L15 L16 to an object offset -0.25 from offset 0.25
sketch "Plate Mount" plane through (0, -10.1, 0) normal (0, 1, 0) x axis (-1, 0, 0)
  line L1 (-26.7296, 114.75) -> (-2.9, 114.75)
  line L2 (-26.7296, 2.0302) -> (-26.7296, 114.75)
  line L3 (-2.9, 2.0302) -> (-26.7296, 2.0302)
  line L4 (-2.9, 114.75) -> (-2.9, 2.0302)
  line L5 (-57, 11.7802) -> (-13, 11.7802)
  line L6 (-57, 101.7802) -> (-57, 11.7802)
  line L7 (-13, 101.7802) -> (-57, 101.7802)
  line L8 (-13, 11.7802) -> (-13, 101.7802)
  line L9 (-35, 11.7802) -> (-35, 1.7802)
  line L10 (-57, 158.7802) -> (-57, 101.7802)
  circle C1 centre (-13, 11.7802) radius 2.125
  circle C2 centre (-13, 101.7802) radius 2.125
  circle C3 centre (-13, 101.7802) radius 4.25
  circle C4 centre (-13, 11.7802) radius 4.25
  circle C5 centre (-57, 158.7802) radius 2.125
  circle C6 centre (-57, 158.7802) radius 4.25
  point P10 (-35, 1.7802)
  point P11 (-35, 1.7802)
  point P12 (-35, 11.7802)
  point P6 (-13, 11.7802)
  point P13 (-13, 11.7802)
  point P9 (-13, 101.7802)
  point P14 (-13, 101.7802)
  point P17 (-57, 158.7802)
  point P18 (-57, 158.7802)
  point P8 (-57, 101.7802)
  point P7 (-57, 11.7802)
  horizontal L5
  vertical L6
  horizontal L7
  vertical L8
  coincident P10 P11
  midpoint L5 P12
  vertical L9
  coincident P6 P13
  coincident P9 P14
  concentric C2 C3
  concentric C1 C4
  equal C3 C4
  equal C1 C2
  perpendicular L7 L10
  concentric C5 C6
  coincident P17 P18
  dimension "d495" distance P8 P9 = 44
  dimension "d496" distance P7 P8 = 90
  dimension "d497" distance P11 P12 = 10
  dimension "d498" diameter C2 = 4.25
  dimension "d499" diameter C3 = 8.5
  dimension "d522" diameter C5 = 4.25
  dimension "d523" diameter C6 = 8.5
  dimension "d524" distance P8 P17 = 57
extrude "Extrude25" cut sketch "Plate Mount" profile of C1 C2 to an object
extrude "Extrude26" sketch "Plate Mount" profile of C1 C2 C3 C4 to an object
chamfer "Chamfer9" distance 2.125 (= "( ( 8.5 - 4.25 ) / 2 ) * 1 mm")
combine "Combine11"
component_insert "Component Insert4"
joint "Assemble3" alignAngle 0 alignOffsetX 0 alignOffsetY 0 alignOffsetZ 0
mirror "Mirror5" mirrorStitchTolerance 0.1 bodies "East Wing"
sketch "Sketch17" plane through (2.9, 0, 0) normal (-1, 0, 0) x axis (0, -1, 0)
  line L1 (10.5, 114.75) -> (10.5, 178.5398)
  line L2 (10.1, 114.75) -> (10.5, 114.75)
  line L3 (10.1, 2.0302) -> (10.1, 114.75)
  line L4 (10.5, 2.0302) -> (10.1, 2.0302)
  line L5 (10.5, -11) -> (10.5, 2.0302)
  line L6 (27.35, -11) -> (10.5, -11)
  line L7 (27.35, -7.85) -> (27.35, -11)
  line L8 (52.65, -7.85) -> (27.35, -7.85)
  line L9 (52.65, -11) -> (52.65, -7.85)
  line L10 (73, -11) -> (52.65, -11)
  line L11 (73, 233.5398) -> (73, -11)
  line L12 (52.65, 233.5398) -> (73, 233.5398)
  line L13 (52.65, 230.3898) -> (52.65, 233.5398)
  line L14 (27.35, 230.3898) -> (52.65, 230.3898)
  line L15 (27.35, 233.5398) -> (27.35, 230.3898)
  line L16 (4, 233.5398) -> (27.35, 233.5398)
  line L17 (4, 178.5398) -> (4, 233.5398)
  line L18 (10.5, 178.5398) -> (4, 178.5398)
  line L19 (30.1, 161.2802) -> (10.5, 161.2802)
  line L20 (30.1, 114.2802) -> (30.1, 161.2802)
  line L21 (10.5, 114.2802) -> (30.1, 114.2802)
  line L22 (25.1, 121.2802) -> (25.1, 154.2802)
  line L23 (30.1, 137.7802) -> (25.1, 137.7802)
  circle C1 centre (12, 223.5398) radius 2.125
  circle C2 centre (16.5, -5) radius 2.125
  circle C3 centre (63.5, -5) radius 2.125
  circle C4 centre (68, 223.5398) radius 2.125
  point P24 (10.5, 161.2802)
  point P27 (10.5, 114.2802)
  point P30 (25.1, 137.7802)
  point P31 (30.1, 137.7802)
  point P28 (25.1, 154.2802)
  coincident L1 P24
  perpendicular L1 L19
  perpendicular L19 L20
  coincident L1 P27
  perpendicular L1 L21
  midpoint L22 P30
  midpoint L20 P31
  horizontal L23
  dimension "d514" distance L20 P28 = 5
  dimension "d515" distance L19 P28 = 7
extrude "Extrude27" cut sketch "Sketch17" profile of L1 L19 L20 L21 to an object
fillet "Fillet32" radius 3
extrude "Extrude28" add of existing geometry to an object offset -1
extrude "Extrude29" cut sketch "Plate Mount" profile of C5 to an object
extrude "Extrude30" cut sketch "Plate Mount" profile of C5 C6 to an object from offset -5
chamfer "Chamfer10" distance 2.125 (= "( ( 8.5 - 4.25 ) / 2 ) * 1 mm")
sketch "Handle" plane through (0, 0, 157.0552) normal (0, 0, 1) x axis (-1, 0, 0)
  line L1 (-20, 75.5663) -> (-23.886, 66.3522)
  line L2 (-35, 68.6) -> (-35, 40)
  line L3 (-35, 78.6) -> (-35, 68.6)
  line L4 (-24.7072, 72.125) -> (-23.4974, 67.2736)
  line L5 (-24.7072, 72.125) -> (-21.943, 70.9592)
  line L6 (-24.7072, 72.125) -> (-20.3886, 74.6449)
  line L7 (-35, 75.5663) -> (-20, 75.5663)
  line L8 (-21.1547, 77.5663) -> (-20, 75.5663)
  line L9 (-35, 77.5663) -> (-21.1547, 77.5663)
  circle C1 centre (-35, 40) radius 28.6
  circle C2 centre (-35, 40) radius 25.3
  arc A1 centre (-35, 40) radius 38.6 clockwise from (-35, 78.6) to (-20, 75.5663)
  point P3 (-23.886, 66.3522)
  point P2 (-35, 40)
  point P5 (-35, 40)
  point P6 (-35, 68.6)
  point P7 (-35, 40)
  point P8 (-35, 78.6)
  point P9 (-23.4974, 67.2736)
  point P11 (-21.943, 70.9592)
  point P12 (-20.3886, 74.6449)
  point P10 (-24.7072, 72.125)
  point P13 (-24.7072, 72.125)
  point P14 (-35, 75.5663)
  point P16 (-35, 77.5663)
  point P4 (-20, 75.5663)
  coincident C1 P3
  coincident P2 L1
  coincident P2 P5
  coincident C1 P6
  vertical L2
  parallel L2 L3
  coincident P5 P7
  coincident L3 P8
  coincident L1 P9
  midpoint L1 P11
  perpendicular L1 L5
  symmetric P9 L5 P12
  symmetric P10 L5 P13
  coincident L3 P14
  perpendicular L3 L7
  perpendicular L3 L9
  coincident L3 P16
  dimension "d531" distance C1 A1 = 10
  dimension "d532" distance P4 L2 = 15
  dimension "d535" distance P10 P11 = 3
  dimension "d536" distance P3 P9 = 1
  dimension "d545" angle L7 L8 = 60
  dimension "d546" distance P14 L9 = 2
extrude "Extrude31" sketch "Handle" profile of C1 L1 L3 A1 L4 L6 L7 L8 L9 blind 90 from offset 15 bodies "Handle"
extrude "Extrude32" sketch "Handle" profile of L1 L4 L6 to an object offset -10 from offset 10
fillet "Fillet33" radius 2
fillet "Fillet34" radius 2
mirror "Mirror7" mirrorStitchTolerance 0.1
